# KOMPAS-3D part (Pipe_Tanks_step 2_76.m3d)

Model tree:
1. X Axis
2. Y Axis
3. Z Axis  (labels: T-Bend Dn 50; Pipe Dn 50; Bend 90 Dn 50)
     Òîëùèíà ñòåíêè 1 = 1

Referenced files in C:\Documents and Settings\kashirsky\Мои документы\Camtasia Studio\Pipelines3D\Tanks\: Tanks_step 2.a3d
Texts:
  Pipe Dn 50
  Steel ASTM A295
  Three Point Plane
  Plane at Angle
  Line and Point Plane
  Axis through Two Vertices
  Axis of Feature
  Axis of Conical Surface
  Axis through Edge
  Trim by Surface
  Trim by Sketch
  Feature with No History
  Intersection Axis of Two Planes
  Two Line Plane
  Line and Face Plane
  Bend by line
  Hole in sheet body
  Cut in sheet body
  Point in CM
  Linear Dimension from Line to Point
  Surface Finish Symbol
  Geometric Tolerance Symbol
  Leader #1
  Leader #2
  Leader #3
  Shape Deviations and Datum
  Node point number
  Mark of coordination axis
  Node point designation
  Mark/Reference designation with leader
  Mark/reference designation on line
  Mark/Reference designation without leader
  T-Bend Dn 50
  Bend 90 Dn 50
  Plane of section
